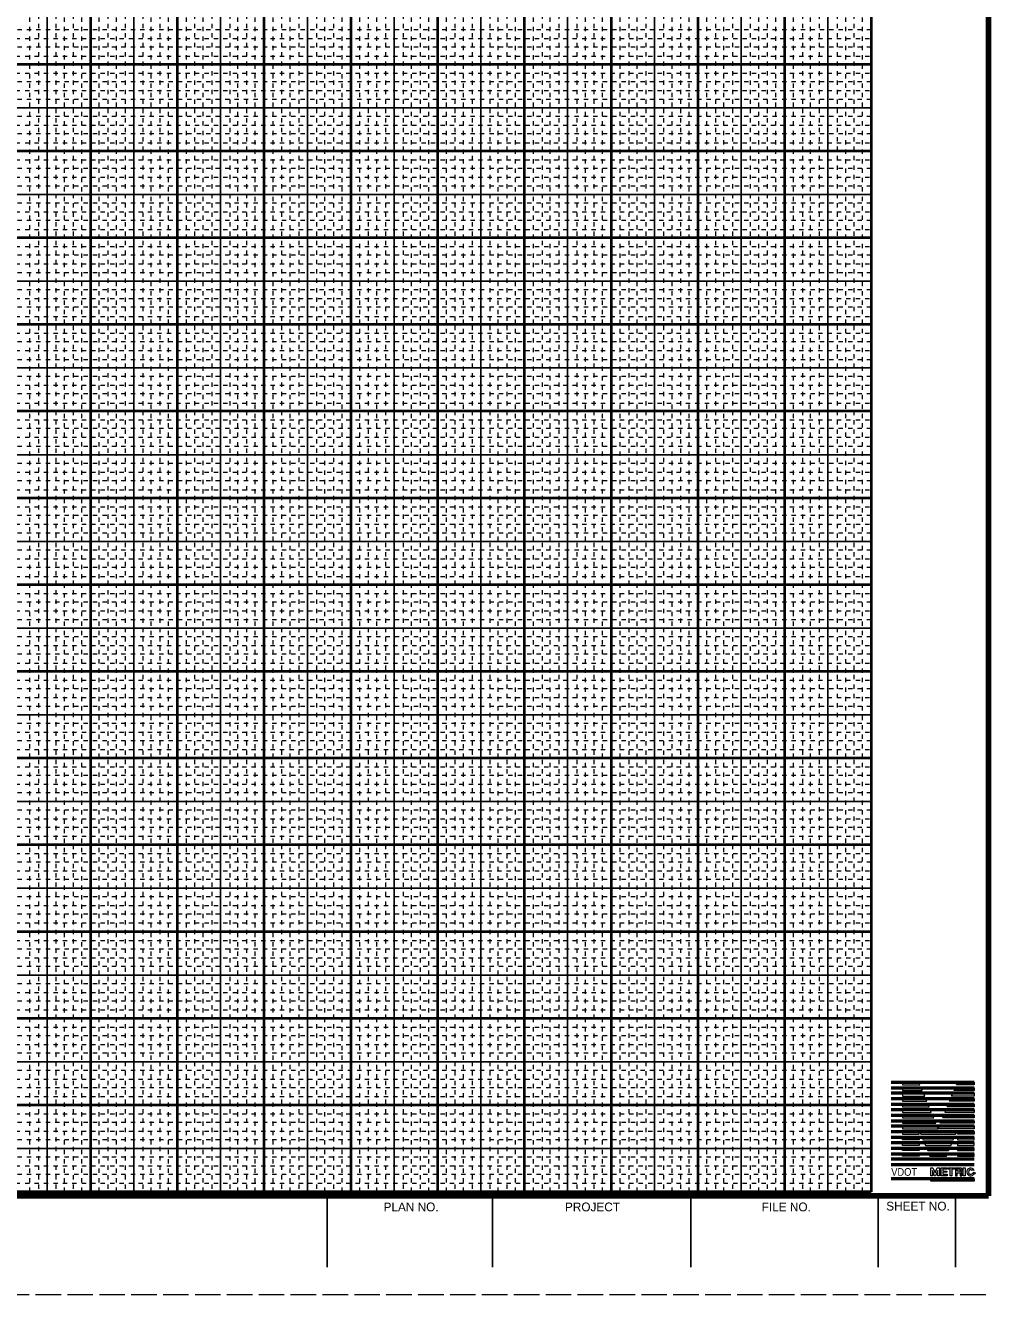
# Model space of a CAD drawing. Extents: x 224742 to 224831, y 224746 to 230645.
# Drawn here: x 224808.86 to 224831.11, y 225453.99 to 225483.26 of the extents above; entities that cross this region are included whole.
import ezdxf
from ezdxf.enums import TextEntityAlignment as Align

# ---------------------------------------------------------------- set-up
doc = ezdxf.new("R2010")
doc.units = 0
doc.header["$LTSCALE"] = 0.098
doc.header["$PDMODE"] = 32
doc.header["$PDSIZE"] = 0.049
doc.linetypes.add('DOTTED', pattern=[1.5, 0.3, -1.2])
doc.linetypes.add('LONG_DASHED', pattern=[7.5, 6, -1.5])
for name, color, linetype, lineweight in [('59', 7, 'DOTTED', 13), ('60', 7, 'Continuous', 40), ('61', 7, 'Continuous', 13), ('63', 7, 'LONG_DASHED', 13)]:
    doc.layers.add(name, color=color, linetype=linetype, lineweight=lineweight)

msp = doc.modelspace()

# ---------------------------------------------------------------- linework, layer by layer
at = {"layer": '59'}
for p, q in [((224808.9648, 225456.3649), (224808.9648, 225506.3649)), ((224809.1648, 225506.3649), (224809.1648, 225456.3649)), ((224809.5648, 225506.3649), (224809.5648, 225456.3649)), ((224809.7648, 225456.3649), (224809.7648, 225506.3649)), ((224809.9648, 225506.3649), (224809.9648, 225456.3649)), ((224810.1648, 225456.3649), (224810.1648, 225506.3649)), ((224810.5648, 225456.3649), (224810.5648, 225506.3649)), ((224810.7648, 225506.3649), (224810.7648, 225456.3649)), ((224810.9648, 225456.3649), (224810.9648, 225506.3649)), ((224811.1648, 225506.3649), (224811.1648, 225456.3649)), ((224811.5748, 225506.3649), (224811.5748, 225456.3649)), ((224811.7648, 225456.3649), (224811.7648, 225506.3649)), ((224811.9648, 225506.3649), (224811.9648, 225456.3649)), ((224812.1648, 225456.3649), (224812.1648, 225506.3649)), ((224812.5748, 225456.3649), (224812.5748, 225506.3649)), ((224812.7648, 225506.3649), (224812.7648, 225456.3649)), ((224812.9648, 225456.3649), (224812.9648, 225506.3649)), ((224813.1648, 225506.3649), (224813.1648, 225456.3649)), ((224813.5748, 225506.3649), (224813.5748, 225456.3649)), ((224813.7648, 225456.3649), (224813.7648, 225506.3649)), ((224813.9648, 225506.3649), (224813.9648, 225456.3649)), ((224814.1648, 225456.3649), (224814.1648, 225506.3649)), ((224814.5748, 225456.3649), (224814.5748, 225506.3649)), ((224814.7648, 225506.3649), (224814.7648, 225456.3649)), ((224814.9648, 225456.3649), (224814.9648, 225506.3649)), ((224815.1648, 225506.3649), (224815.1648, 225456.3649)), ((224815.5748, 225506.3649), (224815.5748, 225456.3649)), ((224815.7648, 225456.3649), (224815.7648, 225506.3649)), ((224815.9648, 225506.3649), (224815.9648, 225456.3649)), ((224816.1648, 225456.3649), (224816.1648, 225506.3649)), ((224816.5748, 225456.3649), (224816.5748, 225506.3649)), ((224816.7648, 225506.3649), (224816.7648, 225456.3649)), ((224816.9648, 225456.3649), (224816.9648, 225506.3649)), ((224817.1648, 225506.3649), (224817.1648, 225456.3649)), ((224817.5748, 225506.3649), (224817.5748, 225456.3649)), ((224817.7648, 225456.3649), (224817.7648, 225506.3649)), ((224817.9648, 225506.3649), (224817.9648, 225456.3649)), ((224818.1648, 225456.3649), (224818.1648, 225506.3649)), ((224818.5748, 225456.3649), (224818.5748, 225506.3649)), ((224818.7648, 225506.3649), (224818.7648, 225456.3649)), ((224818.9648, 225456.3649), (224818.9648, 225506.3649)), ((224819.1648, 225506.3649), (224819.1648, 225456.3649)), ((224819.5748, 225506.3649), (224819.5748, 225456.3649)), ((224819.7648, 225456.3649), (224819.7648, 225506.3649)), ((224819.9648, 225506.3649), (224819.9648, 225456.3649)), ((224820.1648, 225456.3649), (224820.1648, 225506.3649)), ((224820.5748, 225456.3649), (224820.5748, 225506.3649)), ((224820.7748, 225506.3649), (224820.7748, 225456.3649)), ((224820.9648, 225456.3649), (224820.9648, 225506.3649)), ((224821.1648, 225506.3649), (224821.1648, 225456.3649)), ((224821.5748, 225506.3649), (224821.5748, 225456.3649)), ((224821.7748, 225456.3649), (224821.7748, 225506.3649)), ((224821.9648, 225506.3649), (224821.9648, 225456.3649)), ((224822.1648, 225456.3649), (224822.1648, 225506.3649)), ((224822.5748, 225456.3649), (224822.5748, 225506.3649)), ((224822.7748, 225506.3649), (224822.7748, 225456.3649)), ((224822.9648, 225456.3649), (224822.9648, 225506.3649)), ((224823.1648, 225506.3649), (224823.1648, 225456.3649)), ((224823.5748, 225506.3649), (224823.5748, 225456.3649)), ((224823.7748, 225456.3649), (224823.7748, 225506.3649)), ((224823.9648, 225506.3649), (224823.9648, 225456.3649)), ((224824.1648, 225456.3649), (224824.1648, 225506.3649)), ((224824.5748, 225456.3649), (224824.5748, 225506.3649)), ((224824.7748, 225506.3649), (224824.7748, 225456.3649)), ((224824.9648, 225456.3649), (224824.9648, 225506.3649)), ((224825.1648, 225506.3649), (224825.1648, 225456.3649)), ((224825.5748, 225506.3649), (224825.5748, 225456.3649)), ((224825.7748, 225456.3649), (224825.7748, 225506.3649)), ((224825.9648, 225506.3649), (224825.9648, 225456.3649)), ((224826.1648, 225456.3649), (224826.1648, 225506.3649)), ((224826.5748, 225456.3649), (224826.5748, 225506.3649)), ((224826.7748, 225506.3649), (224826.7748, 225456.3649)), ((224826.9648, 225456.3649), (224826.9648, 225506.3649)), ((224827.1648, 225506.3649), (224827.1648, 225456.3649)), ((224827.5748, 225506.3649), (224827.5748, 225456.3649)), ((224827.7748, 225456.3649), (224827.7748, 225506.3649)), ((224827.9648, 225506.3649), (224827.9648, 225456.3649)), ((224828.1648, 225456.3649), (224828.1648, 225506.3649)), ((224828.3648, 225483.1649), (224748.3648, 225483.1649)), ((224748.3648, 225482.9649), (224828.3648, 225482.9649)), ((224828.3648, 225482.7649), (224748.3648, 225482.7649)), ((224748.3648, 225482.5549), (224828.3648, 225482.5549)), ((224748.3648, 225482.1649), (224828.3648, 225482.1649)), ((224828.3648, 225481.9649), (224748.3648, 225481.9649)), ((224748.3648, 225481.7649), (224828.3648, 225481.7649)), ((224828.3648, 225481.5549), (224748.3648, 225481.5549)), ((224828.3648, 225481.1649), (224748.3648, 225481.1649)), ((224748.3648, 225480.9649), (224828.3648, 225480.9649)), ((224828.3648, 225480.7649), (224748.3648, 225480.7649)), ((224748.3648, 225480.5549), (224828.3648, 225480.5549)), ((224748.3648, 225480.1649), (224828.3648, 225480.1649)), ((224828.3648, 225479.9649), (224748.3648, 225479.9649)), ((224748.3648, 225479.7649), (224828.3648, 225479.7649)), ((224828.3648, 225479.5549), (224748.3648, 225479.5549)), ((224828.3648, 225479.1649), (224748.3648, 225479.1649)), ((224748.3648, 225478.9649), (224828.3648, 225478.9649)), ((224828.3648, 225478.7649), (224748.3648, 225478.7649)), ((224748.3648, 225478.5549), (224828.3648, 225478.5549)), ((224748.3648, 225478.1649), (224828.3648, 225478.1649)), ((224828.3648, 225477.9649), (224748.3648, 225477.9649)), ((224748.3648, 225477.7649), (224828.3648, 225477.7649)), ((224828.3648, 225477.5549), (224748.3648, 225477.5549)), ((224828.3648, 225477.1649), (224748.3648, 225477.1649)), ((224748.3648, 225476.9649), (224828.3648, 225476.9649)), ((224828.3648, 225476.7649), (224748.3648, 225476.7649)), ((224748.3648, 225476.5549), (224828.3648, 225476.5549)), ((224748.3648, 225476.1649), (224828.3648, 225476.1649)), ((224828.3648, 225475.9649), (224748.3648, 225475.9649)), ((224748.3648, 225475.7649), (224828.3648, 225475.7649)), ((224828.3648, 225475.5549), (224748.3648, 225475.5549)), ((224828.3648, 225475.1649), (224748.3648, 225475.1649)), ((224748.3648, 225474.9649), (224828.3648, 225474.9649)), ((224828.3648, 225474.7649), (224748.3648, 225474.7649)), ((224748.3648, 225474.5549), (224828.3648, 225474.5549)), ((224748.3648, 225474.1649), (224828.3648, 225474.1649)), ((224828.3648, 225473.9649), (224748.3648, 225473.9649)), ((224748.3648, 225473.7649), (224828.3648, 225473.7649)), ((224828.3648, 225473.5549), (224748.3648, 225473.5549)), ((224828.3648, 225473.1649), (224748.3648, 225473.1649)), ((224748.3648, 225472.9649), (224828.3648, 225472.9649)), ((224828.3648, 225472.7649), (224748.3648, 225472.7649)), ((224748.3648, 225472.5549), (224828.3648, 225472.5549)), ((224748.3648, 225472.1649), (224828.3648, 225472.1649)), ((224828.3648, 225471.9649), (224748.3648, 225471.9649)), ((224748.3648, 225471.7649), (224828.3648, 225471.7649)), ((224828.3648, 225471.5549), (224748.3648, 225471.5549)), ((224828.3648, 225471.1649), (224748.3648, 225471.1649)), ((224748.3648, 225470.9649), (224828.3648, 225470.9649)), ((224828.3648, 225470.7649), (224748.3648, 225470.7649)), ((224748.3648, 225470.5549), (224828.3648, 225470.5549)), ((224748.3648, 225470.1649), (224828.3648, 225470.1649)), ((224828.3648, 225469.9649), (224748.3648, 225469.9649)), ((224748.3648, 225469.7649), (224828.3648, 225469.7649)), ((224828.3648, 225469.5549), (224748.3648, 225469.5549)), ((224828.3648, 225469.1649), (224748.3648, 225469.1649)), ((224748.3648, 225468.9649), (224828.3648, 225468.9649)), ((224828.3648, 225468.7649), (224748.3648, 225468.7649)), ((224748.3648, 225468.5549), (224828.3648, 225468.5549)), ((224748.3648, 225468.1649), (224828.3648, 225468.1649)), ((224828.3648, 225467.9649), (224748.3648, 225467.9649)), ((224748.3648, 225467.7649), (224828.3648, 225467.7649)), ((224828.3648, 225467.5549), (224748.3648, 225467.5549)), ((224828.3648, 225467.1649), (224748.3648, 225467.1649)), ((224748.3648, 225466.9649), (224828.3648, 225466.9649)), ((224828.3648, 225466.7649), (224748.3648, 225466.7649)), ((224748.3648, 225466.5649), (224828.3648, 225466.5649)), ((224748.3648, 225466.1649), (224828.3648, 225466.1649)), ((224828.3648, 225465.9649), (224748.3648, 225465.9649)), ((224748.3648, 225465.7649), (224828.3648, 225465.7649)), ((224828.3648, 225465.5649), (224748.3648, 225465.5649)), ((224828.3648, 225465.1649), (224748.3648, 225465.1649)), ((224748.3648, 225464.9649), (224828.3648, 225464.9649)), ((224828.3648, 225464.7649), (224748.3648, 225464.7649)), ((224748.3648, 225464.5649), (224828.3648, 225464.5649)), ((224748.3648, 225464.1649), (224828.3648, 225464.1649)), ((224828.3648, 225463.9649), (224748.3648, 225463.9649)), ((224748.3648, 225463.7649), (224828.3648, 225463.7649)), ((224828.3648, 225463.5649), (224748.3648, 225463.5649)), ((224828.3648, 225463.1649), (224748.3648, 225463.1649)), ((224748.3648, 225462.9649), (224828.3648, 225462.9649)), ((224828.3648, 225462.7649), (224748.3648, 225462.7649)), ((224748.3648, 225462.5649), (224828.3648, 225462.5649)), ((224748.3648, 225462.1649), (224828.3648, 225462.1649)), ((224828.3648, 225461.9649), (224748.3648, 225461.9649)), ((224748.3648, 225461.7649), (224828.3648, 225461.7649)), ((224828.3648, 225461.5649), (224748.3648, 225461.5649)), ((224828.3648, 225461.1649), (224748.3648, 225461.1649)), ((224748.3648, 225460.9649), (224828.3648, 225460.9649)), ((224828.3648, 225460.7649), (224748.3648, 225460.7649)), ((224748.3648, 225460.5649), (224828.3648, 225460.5649)), ((224748.3648, 225460.1649), (224828.3648, 225460.1649)), ((224828.3648, 225459.9649), (224748.3648, 225459.9649)), ((224748.3648, 225459.7649), (224828.3648, 225459.7649)), ((224828.3648, 225459.5649), (224748.3648, 225459.5649)), ((224828.3648, 225459.1649), (224748.3648, 225459.1649)), ((224748.3648, 225458.9649), (224828.3648, 225458.9649)), ((224828.3648, 225458.7649), (224748.3648, 225458.7649)), ((224748.3648, 225458.5649), (224828.3648, 225458.5649)), ((224748.3648, 225458.1649), (224828.3648, 225458.1649)), ((224828.3648, 225457.9649), (224748.3648, 225457.9649)), ((224748.3648, 225457.7649), (224828.3648, 225457.7649)), ((224828.3648, 225457.5649), (224748.3648, 225457.5649)), ((224828.3648, 225457.1649), (224748.3648, 225457.1649)), ((224748.3648, 225456.9649), (224828.3648, 225456.9649)), ((224828.3648, 225456.7649), (224748.3648, 225456.7649)), ((224748.3648, 225456.5649), (224828.3648, 225456.5649))]:
    msp.add_line(p, q, dxfattribs=at)
at = {"layer": '59', "linetype": 'Continuous', "lineweight": 25}
for p, q in [((224809.3648, 225456.3649), (224809.3648, 225506.3649)), ((224811.3648, 225456.3649), (224811.3648, 225506.3649)), ((224813.3648, 225456.3649), (224813.3648, 225506.3649)), ((224815.3648, 225456.3649), (224815.3648, 225506.3649)), ((224817.3648, 225456.3649), (224817.3648, 225506.3649)), ((224819.3648, 225456.3649), (224819.3648, 225506.3649)), ((224821.3648, 225456.3649), (224821.3648, 225506.3649)), ((224823.3648, 225456.3649), (224823.3648, 225506.3649)), ((224825.3648, 225456.3649), (224825.3648, 225506.3649)), ((224827.3648, 225456.3649), (224827.3648, 225506.3649)), ((224748.3648, 225481.3649), (224828.3648, 225481.3649)), ((224748.3648, 225479.3649), (224828.3648, 225479.3649)), ((224748.3648, 225477.3649), (224828.3648, 225477.3649)), ((224748.3648, 225475.3649), (224828.3648, 225475.3649)), ((224748.3648, 225473.3649), (224828.3648, 225473.3649)), ((224748.3648, 225471.3649), (224828.3648, 225471.3649)), ((224748.3648, 225469.3649), (224828.3648, 225469.3649)), ((224748.3648, 225467.3649), (224828.3648, 225467.3649)), ((224748.3648, 225465.3649), (224828.3648, 225465.3649)), ((224748.3648, 225463.3649), (224828.3648, 225463.3649)), ((224748.3648, 225461.3649), (224828.3648, 225461.3649)), ((224748.3648, 225459.3649), (224828.3648, 225459.3649)), ((224748.3648, 225457.3649), (224828.3648, 225457.3649))]:
    msp.add_line(p, q, dxfattribs=at)
at = {"layer": '60'}
for p, q in [((224810.3648, 225506.3649), (224810.3648, 225456.3649)), ((224812.3648, 225506.3649), (224812.3648, 225456.3649)), ((224814.3648, 225506.3649), (224814.3648, 225456.3649)), ((224816.3648, 225506.3649), (224816.3648, 225456.3649)), ((224818.3648, 225506.3649), (224818.3648, 225456.3649)), ((224820.3648, 225506.3649), (224820.3648, 225456.3649)), ((224822.3648, 225506.3649), (224822.3648, 225456.3649)), ((224824.3648, 225506.3649), (224824.3648, 225456.3649)), ((224826.3648, 225506.3649), (224826.3648, 225456.3649)), ((224828.3648, 225506.3649), (224828.3648, 225456.3649)), ((224828.3648, 225482.3649), (224748.3648, 225482.3649)), ((224828.3648, 225480.3649), (224748.3648, 225480.3649)), ((224828.3648, 225478.3649), (224748.3648, 225478.3649)), ((224828.3648, 225476.3649), (224748.3648, 225476.3649)), ((224828.3648, 225474.3649), (224748.3648, 225474.3649)), ((224828.3648, 225472.3649), (224748.3648, 225472.3649)), ((224828.3648, 225470.3649), (224748.3648, 225470.3649)), ((224828.3648, 225468.3649), (224748.3648, 225468.3649)), ((224828.3648, 225466.3649), (224748.3648, 225466.3649)), ((224828.3648, 225464.3649), (224748.3648, 225464.3649)), ((224828.3648, 225462.3649), (224748.3648, 225462.3649)), ((224828.3648, 225460.3649), (224748.3648, 225460.3649)), ((224828.3648, 225458.3649), (224748.3648, 225458.3649)), ((224828.3648, 225456.3649), (224748.3648, 225456.3649))]:
    msp.add_line(p, q, dxfattribs=at)
at = {"layer": '61', "lineweight": 158}
for p, q in [((224831.0648, 225510.1249), (224831.0648, 225456.2749)), ((224831.0648, 225456.2749), (224745.7148, 225456.2749))]:
    msp.add_line(p, q, dxfattribs=at)
at = {"layer": '61', "lineweight": 53}
for p, q in [((224828.8248, 225458.8949), (224830.7348, 225458.8949)), ((224828.8248, 225458.7649), (224830.7348, 225458.7649)), ((224828.8248, 225458.6449), (224830.7348, 225458.6449)), ((224828.8248, 225458.5149), (224830.7348, 225458.5149)), ((224828.8248, 225458.3849), (224830.7348, 225458.3849)), ((224828.8248, 225458.2649), (224830.7348, 225458.2649)), ((224828.8248, 225458.1349), (224830.7348, 225458.1349)), ((224828.8248, 225458.0049), (224830.7348, 225458.0049)), ((224828.8248, 225457.8849), (224830.7348, 225457.8849)), ((224828.8248, 225457.7549), (224830.7348, 225457.7549)), ((224828.8248, 225457.6249), (224830.7348, 225457.6249)), ((224828.8248, 225457.5049), (224830.7348, 225457.5049)), ((224828.8248, 225457.3749), (224830.7348, 225457.3749)), ((224828.8248, 225457.2449), (224830.7348, 225457.2449)), ((224828.8248, 225457.1249), (224830.7348, 225457.1249)), ((224828.8248, 225456.9949), (224830.7348, 225456.9949)), ((224828.8248, 225456.6749), (224830.7348, 225456.6749))]:
    msp.add_line(p, q, dxfattribs=at)
at = {"layer": '61'}
for p, q in [((224829.0848, 225458.0749), (224829.8048, 225458.0749)), ((224830.7348, 225458.0749), (224830.0148, 225458.0749)), ((224829.0848, 225457.9449), (224829.8548, 225457.9449)), ((224829.8848, 225457.8849), (224829.9048, 225457.8149)), ((224829.9348, 225457.8849), (224829.9048, 225457.8149)), ((224830.7348, 225457.9449), (224829.9548, 225457.9449)), ((224830.7348, 225456.8649), (224830.6848, 225456.8649)), ((224830.6948, 225456.7949), (224830.7348, 225456.7949))]:
    msp.add_line(p, q, dxfattribs=at)
at = {"layer": '61', "lineweight": 25}
for p, q in [((224831.0648, 225456.2749), (224815.8248, 225456.2749)), ((224815.8248, 225456.2749), (224815.8248, 225454.6249)), ((224831.0648, 225456.2749), (224815.8248, 225456.2749)), ((224819.6348, 225456.2749), (224819.6348, 225454.6249)), ((224824.2048, 225454.6249), (224824.2048, 225456.2749)), ((224828.5248, 225454.6249), (224828.5248, 225456.2749)), ((224830.3048, 225454.6249), (224830.3048, 225456.2749))]:
    msp.add_line(p, q, dxfattribs=at)
at = {"layer": '61'}
for points in [[(224829.0848, 225458.8949), (224829.0848, 225458.8349), (224829.4848, 225458.8349), (224829.4648, 225458.8949)], [(224829.0848, 225458.7649), (224829.0848, 225458.7049), (224829.5348, 225458.7049), (224829.5148, 225458.7649)], [(224829.0848, 225458.6449), (224829.0848, 225458.5749), (224829.5948, 225458.5749), (224829.5648, 225458.6449)], [(224830.7348, 225458.6449), (224830.7348, 225458.5749), (224830.2148, 225458.5749), (224830.2448, 225458.6449)], [(224830.7348, 225458.7649), (224830.7348, 225458.7049), (224830.2748, 225458.7049), (224830.2948, 225458.7649)], [(224830.7348, 225458.8949), (224830.7348, 225458.8349), (224830.3248, 225458.8349), (224830.3548, 225458.8949)], [(224829.0848, 225458.5149), (224829.0848, 225458.4549), (224829.6448, 225458.4549), (224829.6148, 225458.5149)], [(224829.0848, 225458.3849), (224829.0848, 225458.3249), (224829.6948, 225458.3249), (224829.6748, 225458.3849)], [(224830.7348, 225458.3849), (224830.7348, 225458.3249), (224830.1148, 225458.3249), (224830.1448, 225458.3849)], [(224830.7348, 225458.5149), (224830.7348, 225458.4549), (224830.1648, 225458.4549), (224830.1948, 225458.5149)], [(224829.0848, 225458.2649), (224829.0848, 225458.1949), (224829.7448, 225458.1949), (224829.7248, 225458.2649)], [(224829.0848, 225458.1349), (224829.0848, 225458.0749), (224829.8048, 225458.0749), (224829.7748, 225458.1349)], [(224830.7348, 225458.1349), (224830.7348, 225458.0749), (224830.0148, 225458.0749), (224830.0348, 225458.1349)], [(224830.7348, 225458.2649), (224830.7348, 225458.1949), (224830.0648, 225458.1949), (224830.0848, 225458.2649)], [(224829.0848, 225458.0049), (224829.0848, 225457.9449), (224829.8548, 225457.9449), (224829.8248, 225458.0049)], [(224829.0848, 225457.8849), (224829.0848, 225457.8149), (224829.9048, 225457.8149), (224829.8848, 225457.8849)], [(224829.0848, 225457.7549), (224829.0848, 225457.6949), (224829.4648, 225457.6949), (224829.4648, 225457.7549)], [(224829.4848, 225457.7549), (224829.5048, 225457.6949), (224830.3048, 225457.6949), (224830.3348, 225457.7549)], [(224830.7348, 225457.8849), (224830.7348, 225457.8149), (224829.9048, 225457.8149), (224829.9348, 225457.8849)], [(224830.7348, 225458.0049), (224830.7348, 225457.9449), (224829.9548, 225457.9449), (224829.9848, 225458.0049)], [(224830.7348, 225457.7549), (224830.7348, 225457.6949), (224830.3548, 225457.6949), (224830.3548, 225457.7549)], [(224829.0848, 225457.6249), (224829.4648, 225457.6249), (224829.4648, 225457.5649), (224829.0848, 225457.5649)], [(224829.0848, 225457.5049), (224829.4648, 225457.5049), (224829.4648, 225457.4349), (224829.0848, 225457.4349)], [(224829.5348, 225457.6249), (224829.5548, 225457.5649), (224830.2548, 225457.5649), (224830.2748, 225457.6249)], [(224829.5848, 225457.5049), (224829.6148, 225457.4349), (224830.2048, 225457.4349), (224830.2248, 225457.5049)], [(224830.7348, 225457.6249), (224830.3548, 225457.6249), (224830.3548, 225457.5649), (224830.7348, 225457.5649)], [(224830.7348, 225457.5049), (224830.3548, 225457.5049), (224830.3548, 225457.4349), (224830.7348, 225457.4349)], [(224829.0848, 225457.3749), (224829.4648, 225457.3749), (224829.4648, 225457.3149), (224829.0848, 225457.3149)], [(224829.0848, 225457.2449), (224829.4648, 225457.2449), (224829.4648, 225457.1849), (224829.0848, 225457.1849)], [(224829.6348, 225457.3749), (224829.6648, 225457.3149), (224830.1448, 225457.3149), (224830.1748, 225457.3749)], [(224829.6948, 225457.2449), (224829.7148, 225457.1849), (224830.0948, 225457.1849), (224830.1248, 225457.2449)], [(224830.7348, 225457.3749), (224830.3548, 225457.3749), (224830.3548, 225457.3149), (224830.7348, 225457.3149)], [(224830.7348, 225457.2449), (224830.3548, 225457.2449), (224830.3548, 225457.1849), (224830.7348, 225457.1849)], [(224829.7348, 225456.7349), (224829.7348, 225456.9149), (224829.7848, 225456.9149), (224829.8348, 225456.8049), (224829.8848, 225456.9149), (224829.9348, 225456.9149), (224829.9348, 225456.7349), (224829.8948, 225456.7349), (224829.8948, 225456.8549), (224829.8448, 225456.7349), (224829.8248, 225456.7349), (224829.7748, 225456.8549), (224829.7748, 225456.7349)], [(224829.9748, 225456.7349), (224829.9748, 225456.9149), (224830.1148, 225456.9149), (224830.1148, 225456.8849), (224830.0148, 225456.8849), (224830.0148, 225456.8449), (224830.1048, 225456.8449), (224830.1048, 225456.8149), (224830.0148, 225456.8149), (224830.0148, 225456.7749), (224830.1148, 225456.7749), (224830.1148, 225456.7349)], [(224830.1348, 225456.8849), (224830.1348, 225456.9149), (224830.2848, 225456.9149), (224830.2848, 225456.8849), (224830.2248, 225456.8849), (224830.2248, 225456.7349), (224830.1848, 225456.7349), (224830.1848, 225456.8849)], [(224830.3048, 225456.9149), (224830.3048, 225456.7349), (224830.3448, 225456.7349), (224830.3448, 225456.8049), (224830.3948, 225456.8049), (224830.3948, 225456.8049), (224830.4048, 225456.8049), (224830.4048, 225456.8049), (224830.4048, 225456.8049), (224830.4048, 225456.8049), (224830.4048, 225456.7949), (224830.4148, 225456.7949), (224830.4148, 225456.7849), (224830.4148, 225456.7749), (224830.4148, 225456.7549), (224830.4148, 225456.7549), (224830.4148, 225456.7449), (224830.4148, 225456.7349), (224830.4148, 225456.7349), (224830.4548, 225456.7349), (224830.4548, 225456.7449), (224830.4548, 225456.7449), (224830.4548, 225456.7449), (224830.4548, 225456.7549), (224830.4548, 225456.7849), (224830.4548, 225456.7949), (224830.4448, 225456.8049), (224830.4448, 225456.8149), (224830.4448, 225456.8149), (224830.4448, 225456.8149), (224830.4448, 225456.8149), (224830.4348, 225456.8149), (224830.4348, 225456.8249), (224830.4348, 225456.8249), (224830.4248, 225456.8249), (224830.4248, 225456.8249), (224830.4248, 225456.8249), (224830.3948, 225456.8449), (224830.3448, 225456.8449), (224830.3448, 225456.8849)], [(224830.3048, 225456.9149), (224830.3748, 225456.9149), (224830.3948, 225456.9149), (224830.3948, 225456.9149), (224830.4048, 225456.9149), (224830.4148, 225456.9149), (224830.4148, 225456.9149), (224830.4248, 225456.9149), (224830.4248, 225456.9149), (224830.4248, 225456.9149), (224830.4348, 225456.9149), (224830.4348, 225456.9049), (224830.4448, 225456.9049), (224830.4448, 225456.9049), (224830.4448, 225456.9049), (224830.4548, 225456.8949), (224830.4548, 225456.8949), (224830.4548, 225456.8949), (224830.4548, 225456.8849), (224830.4548, 225456.8849), (224830.4548, 225456.8749), (224830.4548, 225456.8649), (224830.4548, 225456.8649), (224830.4548, 225456.8549), (224830.4548, 225456.8549), (224830.4548, 225456.8549), (224830.4548, 225456.8449), (224830.4548, 225456.8449), (224830.4448, 225456.8449), (224830.4448, 225456.8449), (224830.4448, 225456.8349), (224830.4448, 225456.8349), (224830.4348, 225456.8349), (224830.4348, 225456.8349), (224830.4248, 225456.8249), (224830.4248, 225456.8249), (224830.3948, 225456.8449), (224830.3948, 225456.8449), (224830.4048, 225456.8449), (224830.4048, 225456.8449), (224830.4148, 225456.8449), (224830.4148, 225456.8549), (224830.4148, 225456.8549), (224830.4148, 225456.8549), (224830.4248, 225456.8649), (224830.4248, 225456.8649), (224830.4248, 225456.8649), (224830.4248, 225456.8749), (224830.4148, 225456.8749), (224830.4148, 225456.8749), (224830.4148, 225456.8749), (224830.4148, 225456.8849), (224830.4048, 225456.8849), (224830.4048, 225456.8849), (224830.3948, 225456.8849), (224830.3448, 225456.8849)], [(224830.4848, 225456.7349), (224830.4848, 225456.9149), (224830.5248, 225456.9149), (224830.5248, 225456.7349)], [(224829.7348, 225456.6749), (224830.7348, 225456.6749), (224830.7348, 225456.6149), (224829.7348, 225456.6149)]]:
    msp.add_lwpolyline(points, close=True, dxfattribs=at)
for radius, start, end in [(0.0894, 24.50501, 339.37361), (0.0518, 45.69947, 322.56629)]:
    msp.add_arc((224830.6538, 225456.8221), radius, start, end, dxfattribs=at)
msp.add_point((224830.7348, 225456.7949), dxfattribs=at)
at = {"layer": '63'}
msp.add_lwpolyline([(224831.1148, 225512.3949), (224742.2148, 225512.3949), (224742.2148, 225453.9949), (224831.1148, 225453.9949)], dxfattribs=at)

# ---------------------------------------------------------------- texts
at = {"layer": '61', "width": 0.9}
msp.add_text('VDOT', height=0.1778, dxfattribs=at).set_placement((224828.8248, 225456.7349))
at = {"layer": '61'}
for s, p in [('PLAN NO.', (224817.7557, 225455.9149)), ('PROJECT', (224821.9377, 225455.9149)), ('FILE NO.', (224826.405, 225455.9149)), ('SHEET NO.', (224829.4415, 225455.9341))]:
    msp.add_text(s, height=0.2032, dxfattribs=at).set_placement(p, align=Align.CENTER)

doc.saveas('drawing.dxf')
